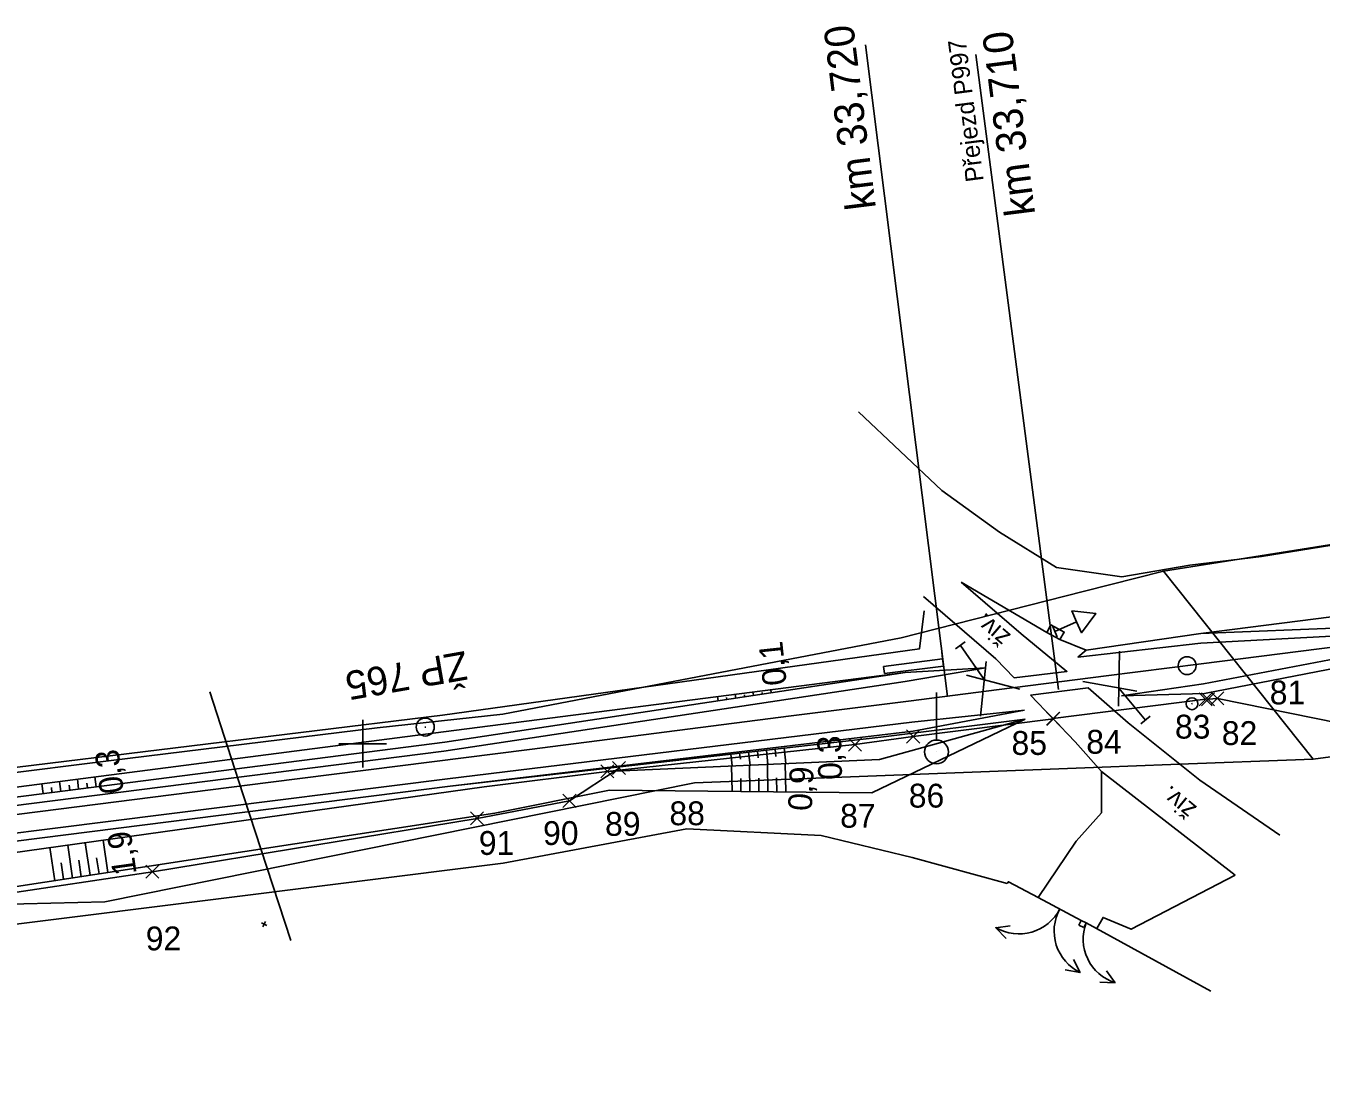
# Model space of a CAD drawing. Extents: x -805011 to -803920, y -1150790 to -1150234.
# Drawn here: x -804628.3 to -804519.6, y -1150528 to -1150439.8 of the extents above; entities that cross this region are included whole.
import ezdxf

# ---------------------------------------------------------------- set-up
doc = ezdxf.new("R2010")
doc.units = 0
for name, color, linetype in [('0381KM032-037P - Vrstva 1', 7, 'Continuous'), ('0381KM032-037P - Vrstva 12', 7, 'Continuous'), ('0381KM032-037P - Vrstva 17', 7, 'Continuous'), ('0381KM032-037P - Vrstva 25', 7, 'Continuous'), ('0381KM032-037P - Vrstva 36', 7, 'Continuous'), ('0381KM032-037P - Vrstva 4', 7, 'Continuous'), ('0381KM032-037P - Vrstva 48', 7, 'Continuous'), ('0381KM032-037P - Vrstva 49', 7, 'Continuous'), ('0381KM032-037P - Vrstva 51', 7, 'Continuous'), ('0381KM032-037P - Vrstva 55', 7, 'Continuous'), ('0381KM032-037P - Vrstva 7', 7, 'Continuous'), ('0381KM032-037P - Vrstva 9', 7, 'Continuous'), ('Default', 7, 'Continuous'), ('hran DP - hran DP', 7, 'Continuous'), ('krizky_1000 - Vrstva 1', 7, 'Continuous'), ('PSR_C2_2_Lomove_body_Vimperk - Vrstva 60', 7, 'Continuous'), ('PSR_C2_2_trasa_Vimperk - Kabelová trasa', 7, 'Continuous'), ('vyt_sit - stávající', 7, 'Continuous')]:
    doc.layers.add(name, color=color, linetype=linetype)

msp = doc.modelspace()

# ---------------------------------------------------------------- linework, layer by layer
at = {"layer": '0381KM032-037P - Vrstva 1'}
msp.add_lwpolyline([(-804485.9, -1150487.74), (-804508.11, -1150490.55), (-804529.67, -1150493.3), (-804537.63, -1150494.31), (-804546.61, -1150495.46), (-804554.2, -1150496.42), (-804564.05, -1150497.67), (-804586.01, -1150500.48), (-804607.92, -1150503.26), (-804630.35, -1150506.11), (-804652.65, -1150508.9), (-804675.7, -1150511.78), (-804698.85, -1150514.71), (-804701.61, -1150515.06), (-804722.18, -1150517.67), (-804729.05, -1150518.54), (-804735.1, -1150519.31), (-804744.56, -1150520.5), (-804767.65, -1150523.46), (-804791, -1150526.42)], dxfattribs=at)
at = {"layer": '0381KM032-037P - Vrstva 12'}
for p, q in [((-804542.27, -1150490.03), (-804542.27, -1150490.03)), ((-804541.15, -1150490.64), (-804541.15, -1150490.64))]:
    msp.add_line(p, q, dxfattribs=at)
msp.add_lwpolyline([(-804542.6, -1150490.68), (-804542.27, -1150490.03), (-804541.15, -1150490.64), (-804541.52, -1150491.26), (-804542.6, -1150490.68), (-804542.27, -1150490.03), (-804541.15, -1150490.64), (-804541.52, -1150491.26)], dxfattribs=at)
at = {"layer": '0381KM032-037P - Vrstva 17'}
for p, q in [((-804553.92, -1150509.55), (-804545.93, -1150511.73)), ((-804546.89, -1150515.44), (-804546.02, -1150516.35)), ((-804539.31, -1150515.02), (-804528.85, -1150520.76)), ((-804539.82, -1150519.19), (-804541.07, -1150518.98)), ((-804536.89, -1150520.06), (-804537.59, -1150519.06)), ((-804538.15, -1150520.02), (-804536.89, -1150520.06)), ((-804536.89, -1150520.06), (-804538.15, -1150520.02))]:
    msp.add_line(p, q, dxfattribs=at)
for points in [[(-804368.54, -1150462.33), (-804374.42, -1150462.03), (-804388.45, -1150464.13), (-804427.08, -1150469.25), (-804429.72, -1150469.73), (-804431.75, -1150470.1), (-804437.24, -1150471.08), (-804446.96, -1150472.02), (-804473.97, -1150476), (-804503.76, -1150480.94), (-804524.61, -1150484.28), (-804530.6, -1150485.02), (-804536.33, -1150485.99), (-804541.81, -1150485.21), (-804546.58, -1150482.25), (-804551.41, -1150478.74), (-804558.4, -1150472.14)], [(-804552.89, -1150488.84), (-804553.29, -1150492.03), (-804593.3, -1150497.6), (-804640.86, -1150503.43), (-804657.42, -1150505.51), (-804657.62, -1150505.23), (-804688.14, -1150507.97), (-804701.71, -1150508.32), (-804722.68, -1150510.59), (-804720.85, -1150507.4)], [(-804731.29, -1150527.98), (-804729.95, -1150523.81), (-804721.9, -1150522.89), (-804700.75, -1150520.73), (-804652.77, -1150518.11), (-804588.21, -1150510.02), (-804572.8, -1150507.15), (-804561.55, -1150507.7), (-804553.92, -1150509.55)], [(-804545.93, -1150511.73), (-804545.83, -1150511.58), (-804543.33, -1150512.91)], [(-804546.02, -1150516.35), (-804546.89, -1150515.44), (-804545.68, -1150515.29)], [(-804539.92, -1150515.23), (-804539.73, -1150514.83), (-804539.31, -1150515.02)], [(-804539.92, -1150515.23), (-804539.5, -1150515.43), (-804539.31, -1150515.02)], [(-804541.07, -1150518.98), (-804539.82, -1150519.19), (-804540.38, -1150518.1)]]:
    msp.add_lwpolyline(points, dxfattribs=at)
for centre, start, end in [((-804544.94, -1150512.13), 239.5292, 333.049), ((-804538.17, -1150515.73), 150.9796, 244.4995), ((-804535.73, -1150516.4), 158.9316, 252.4515)]:
    msp.add_arc(centre, 3.83, start, end, dxfattribs=at)
at = {"layer": '0381KM032-037P - Vrstva 25'}
msp.add_lwpolyline([(-804612.83, -1150495.66), (-804610.41, -1150503.1), (-804608.55, -1150508.81), (-804606.04, -1150516.52)], dxfattribs=at)
at = {"layer": '0381KM032-037P - Vrstva 36'}
for p, q in [((-804551.87, -1150499.69), (-804551.87, -1150495.69)), ((-804551.87, -1150500.69), (-804551.87, -1150500.69))]:
    msp.add_line(p, q, dxfattribs=at)
msp.add_circle((-804551.87, -1150500.69), 1, dxfattribs=at)
at = {"layer": '0381KM032-037P - Vrstva 4'}
for p, q in [((-804541.64, -1150495.45), (-804548.57, -1150442.16)), ((-804515.79, -1150490.21), (-804529.7, -1150490.74)), ((-804549.45, -1150491.46), (-804550.27, -1150492.03)), ((-804515.61, -1150490.8), (-804529.7, -1150491.57)), ((-804549.86, -1150491.75), (-804547.86, -1150494.62)), ((-804529.7, -1150491.57), (-804540.01, -1150492.74)), ((-804536.6, -1150496.85), (-804536.52, -1150492.24)), ((-804515.43, -1150492.3), (-804529.48, -1150494.97)), ((-804547.76, -1150493.63), (-804554.49, -1150494.02)), ((-804547.76, -1150493.63), (-804554.48, -1150494.77)), ((-804547.69, -1150493.1), (-804548.16, -1150497.69)), ((-804515.37, -1150493.06), (-804529.38, -1150495.79)), ((-804593.19, -1150500.62), (-804554.48, -1150494.77)), ((-804593.11, -1150499.86), (-804554.49, -1150494.02)), ((-804544.88, -1150495.41), (-804549.34, -1150494.25)), ((-804537.63, -1150494.31), (-804546.61, -1150495.46)), ((-804539.6, -1150494.79), (-804535.05, -1150495.58)), ((-804534.33, -1150498.02), (-804536.56, -1150495.33)), ((-804536.34, -1150495.99), (-804529.48, -1150494.97)), ((-804529.38, -1150495.79), (-804536.34, -1150495.99)), ((-804544.49, -1150497.19), (-804553.94, -1150498.18)), ((-804553.83, -1150498.96), (-804544.49, -1150497.19)), ((-804534.71, -1150498.34), (-804533.94, -1150497.7)), ((-804553.94, -1150498.18), (-804592.89, -1150502.96)), ((-804592.67, -1150503.55), (-804553.83, -1150498.96))]:
    msp.add_line(p, q, dxfattribs=at)
for points in [[(-804540.01, -1150492.74), (-804539.3, -1150492.14), (-804529.7, -1150490.74)], [(-804593.11, -1150499.86), (-804640.49, -1150505.94), (-804687.8, -1150511.91), (-804699.22, -1150512.12)], [(-804593.19, -1150500.62), (-804640.38, -1150506.6), (-804687.82, -1150512.54), (-804699.1, -1150513.12)], [(-804592.89, -1150502.96), (-804640.05, -1150508.88), (-804687.61, -1150514.59), (-804699.07, -1150516.32)], [(-804592.67, -1150503.55), (-804639.94, -1150509.55), (-804687.3, -1150515.71), (-804688.22, -1150515.92)]]:
    msp.add_lwpolyline(points, dxfattribs=at)
at = {"layer": '0381KM032-037P - Vrstva 48'}
for p, q in [((-804568.7, -1150496.17), (-804568.75, -1150495.86)), ((-804567.96, -1150496.06), (-804567.98, -1150495.91)), ((-804567.22, -1150495.94), (-804567.26, -1150495.67)), ((-804566.48, -1150495.83), (-804566.5, -1150495.7)), ((-804565.74, -1150495.72), (-804565.77, -1150495.47)), ((-804570.19, -1150496.39), (-804570.24, -1150496.05)), ((-804569.44, -1150496.28), (-804569.47, -1150496.12)), ((-804569.12, -1150500.87), (-804569.01, -1150501.87)), ((-804568.38, -1150500.79), (-804568.32, -1150501.31)), ((-804567.63, -1150500.7), (-804567.51, -1150501.8)), ((-804566.89, -1150500.62), (-804566.82, -1150501.19)), ((-804566.14, -1150500.53), (-804566.01, -1150501.74)), ((-804565.4, -1150500.45), (-804565.33, -1150501.07)), ((-804564.65, -1150500.36), (-804564.5, -1150501.67)), ((-804569.02, -1150504), (-804569.05, -1150501.87)), ((-804567.52, -1150504.01), (-804567.55, -1150501.8)), ((-804566.02, -1150504.03), (-804566.05, -1150501.74)), ((-804564.51, -1150504.04), (-804564.55, -1150501.67)), ((-804626.81, -1150504.19), (-804626.92, -1150503.36)), ((-804625.33, -1150504), (-804625.43, -1150503.17)), ((-804624.58, -1150503.9), (-804624.63, -1150503.49)), ((-804623.84, -1150503.8), (-804623.94, -1150502.98)), ((-804623.09, -1150503.71), (-804623.15, -1150503.3)), ((-804622.35, -1150503.61), (-804622.46, -1150502.79)), ((-804568.27, -1150504.01), (-804568.28, -1150502.92)), ((-804566.77, -1150504.02), (-804566.78, -1150502.9)), ((-804565.26, -1150504.03), (-804565.28, -1150502.87)), ((-804626.07, -1150504.09), (-804626.12, -1150503.68)), ((-804625.83, -1150511.5), (-804626.24, -1150508.72)), ((-804624.35, -1150511.27), (-804624.75, -1150508.52)), ((-804622.87, -1150511.04), (-804623.27, -1150508.31)), ((-804621.38, -1150510.81), (-804621.78, -1150508.1)), ((-804625.09, -1150511.38), (-804625.29, -1150510)), ((-804623.61, -1150511.16), (-804623.81, -1150509.78)), ((-804622.12, -1150510.93), (-804622.33, -1150509.57))]:
    msp.add_line(p, q, dxfattribs=at)
at = {"layer": '0381KM032-037P - Vrstva 49'}
for p, q in [((-804554.49, -1150494.02), (-804593.11, -1150499.86)), ((-804544.42, -1150497.94), (-804556.53, -1150499.44)), ((-804608.49, -1150515.04), (-804608.04, -1150515.25)), ((-804608.15, -1150514.92), (-804608.37, -1150515.37))]:
    msp.add_line(p, q, dxfattribs=at)
for points in [[(-804541.81, -1150485.21), (-804536.33, -1150485.99), (-804530.6, -1150485.02), (-804524.61, -1150484.28), (-804503.76, -1150480.94), (-804473.97, -1150476), (-804446.96, -1150472.02), (-804437.24, -1150471.08), (-804431.75, -1150470.1), (-804429.72, -1150469.73), (-804427.08, -1150469.25), (-804388.45, -1150464.13), (-804374.42, -1150462.03), (-804368.54, -1150462.33), (-804346.87, -1150460.56), (-804338.71, -1150460.38), (-804328.85, -1150461.67), (-804323.06, -1150462.29), (-804320.34, -1150463.27)], [(-804529.7, -1150490.74), (-804539.3, -1150492.14), (-804541.52, -1150491.26), (-804542.6, -1150490.68), (-804549.8, -1150486.44)], [(-804516.1, -1150489.01), (-804529.7, -1150490.74)], [(-804554.49, -1150494.02), (-804593.21, -1150499.01), (-804640.53, -1150505.12), (-804688.31, -1150508.22), (-804703.24, -1150508.74), (-804722.68, -1150510.59)], [(-804544.42, -1150497.94), (-804556.65, -1150501.33), (-804579.48, -1150502.32), (-804589.81, -1150503.62), (-804675.11, -1150515.57), (-804678.92, -1150516.15)], [(-804544.42, -1150497.94), (-804557.28, -1150504.11), (-804579.29, -1150503.91), (-804588.92, -1150505.83), (-804639.29, -1150513.56), (-804678.92, -1150516.15)], [(-804593.11, -1150499.86), (-804640.49, -1150505.94), (-804687.8, -1150511.91), (-804699.22, -1150512.12)], [(-804556.53, -1150499.44), (-804592.67, -1150503.55), (-804639.94, -1150509.55), (-804678.92, -1150516.15)]]:
    msp.add_lwpolyline(points, dxfattribs=at)
at = {"layer": '0381KM032-037P - Vrstva 51'}
for p, q in [((-804544.77, -1150490.77), (-804549.8, -1150486.44)), ((-804546.9, -1150492.89), (-804552.96, -1150487.64)), ((-804542.14, -1150490.12), (-804541.74, -1150491.03)), ((-804545.36, -1150494.48), (-804546.9, -1150492.89)), ((-804540.22, -1150499.84), (-804543.98, -1150495.94))]:
    msp.add_line(p, q, dxfattribs=at)
for points in [[(-804541.94, -1150490.58), (-804540.11, -1150489.77), (-804539.71, -1150490.69), (-804538.51, -1150489.07), (-804540.51, -1150488.86), (-804540.11, -1150489.77)], [(-804545.36, -1150494.48), (-804540.93, -1150493.94), (-804544.77, -1150490.77)], [(-804543.98, -1150495.94), (-804539.14, -1150495.31), (-804535.78, -1150498.25)], [(-804535.78, -1150498.25), (-804529.76, -1150503.07), (-804523.07, -1150507.67)], [(-804540.22, -1150499.84), (-804538.01, -1150502.34), (-804526.8, -1150511.03)], [(-804538.01, -1150502.34), (-804538.01, -1150505.79), (-804540.15, -1150508.19), (-804543.33, -1150512.91), (-804539.73, -1150514.83)], [(-804538.41, -1150515.52), (-804537.89, -1150514.57), (-804535.54, -1150515.57), (-804526.8, -1150511.03)]]:
    msp.add_lwpolyline(points, dxfattribs=at)
at = {"layer": '0381KM032-037P - Vrstva 55'}
msp.add_line((-804532.83, -1150485.53), (-804520.26, -1150501.29), dxfattribs=at)
at = {"layer": '0381KM032-037P - Vrstva 7'}
msp.add_line((-804530.38, -1150496.64), (-804530.48, -1150496.66), dxfattribs=at)
for centre, radius in [((-804530.84, -1150493.45), 0.75), ((-804530.43, -1150496.65), 0.5)]:
    msp.add_circle(centre, radius, dxfattribs=at)
at = {"layer": '0381KM032-037P - Vrstva 9'}
for p, q in [((-804550.95, -1150496.05), (-804557.83, -1150441.36)), ((-804551.35, -1150492.89), (-804551.42, -1150492.3)), ((-804551.35, -1150492.89), (-804556.31, -1150493.51)), ((-804556.31, -1150493.51), (-804556.24, -1150494.1)), ((-804556.24, -1150494.1), (-804551.28, -1150493.49)), ((-804551.28, -1150493.49), (-804551.35, -1150492.89))]:
    msp.add_line(p, q, dxfattribs=at)
at = {"layer": 'hran DP - hran DP'}
for p, q in [((-804532.83, -1150485.53), (-804473.24, -1150476.04)), ((-804539.55, -1150487.24), (-804532.83, -1150485.53)), ((-804554.84, -1150491.12), (-804539.55, -1150487.24)), ((-804574.54, -1150494.89), (-804554.84, -1150491.12)), ((-804588.25, -1150497.51), (-804574.54, -1150494.89)), ((-804477.16, -1150495.64), (-804520.26, -1150501.29)), ((-804598.8, -1150498.68), (-804588.25, -1150497.51)), ((-804621.33, -1150501.45), (-804598.8, -1150498.68)), ((-804520.26, -1150501.29), (-804532.2, -1150501.75)), ((-804634.52, -1150503.07), (-804621.33, -1150501.45)), ((-804537.98, -1150501.97), (-804572.18, -1150503.29)), ((-804532.2, -1150501.75), (-804537.98, -1150501.97)), ((-804572.18, -1150503.29), (-804621.63, -1150513.27)), ((-804621.63, -1150513.27), (-804664.68, -1150514.39))]:
    msp.add_line(p, q, dxfattribs=at)
at = {"layer": 'krizky_1000 - Vrstva 1'}
for points in [[(-804600, -1150498), (-804600, -1150502)], [(-804602, -1150500), (-804598, -1150500)]]:
    msp.add_lwpolyline(points, dxfattribs=at)
at = {"layer": 'PSR_C2_2_Lomove_body_Vimperk - Vrstva 60'}
for p, q in [((-804529.84, -1150496.82), (-804528.74, -1150495.72)), ((-804528.74, -1150496.82), (-804529.84, -1150495.72)), ((-804529.63, -1150496.82), (-804528.53, -1150495.72)), ((-804528.53, -1150496.82), (-804529.63, -1150495.72)), ((-804528.85, -1150496.75), (-804527.75, -1150495.65)), ((-804527.75, -1150496.75), (-804528.85, -1150495.65)), ((-804542.65, -1150498.44), (-804541.55, -1150497.34)), ((-804541.55, -1150498.44), (-804542.65, -1150497.34)), ((-804542.61, -1150498.46), (-804541.51, -1150497.36)), ((-804541.51, -1150498.46), (-804542.61, -1150497.36)), ((-804554.37, -1150499.95), (-804553.27, -1150498.85)), ((-804553.27, -1150499.95), (-804554.37, -1150498.85)), ((-804559.26, -1150500.63), (-804558.16, -1150499.53)), ((-804558.16, -1150500.63), (-804559.26, -1150499.53)), ((-804580.03, -1150502.87), (-804578.93, -1150501.77)), ((-804578.93, -1150502.87), (-804580.03, -1150501.77)), ((-804579.05, -1150502.59), (-804577.95, -1150501.49)), ((-804577.95, -1150502.59), (-804579.05, -1150501.49)), ((-804583.2, -1150505.34), (-804582.1, -1150504.24)), ((-804582.1, -1150505.34), (-804583.2, -1150504.24)), ((-804590.96, -1150506.82), (-804589.86, -1150505.72)), ((-804589.86, -1150506.82), (-804590.96, -1150505.72)), ((-804618.19, -1150511.29), (-804617.09, -1150510.19)), ((-804617.09, -1150511.29), (-804618.19, -1150510.19))]:
    msp.add_line(p, q, dxfattribs=at)
at = {"layer": 'PSR_C2_2_trasa_Vimperk - Kabelová trasa'}
for p, q in [((-804529.29, -1150496.27), (-804542.1, -1150497.89)), ((-804542.06, -1150497.91), (-804553.82, -1150499.4)), ((-804558.71, -1150500.08), (-804579.48, -1150502.32)), ((-804558.71, -1150500.08), (-804553.82, -1150499.4)), ((-804582.65, -1150504.79), (-804578.5, -1150502.04)), ((-804582.65, -1150504.79), (-804590.41, -1150506.27)), ((-804617.64, -1150510.74), (-804590.41, -1150506.27)), ((-804634.35, -1150513.26), (-804617.64, -1150510.74))]:
    msp.add_line(p, q, dxfattribs=at)
msp.add_lwpolyline([(-804529.08, -1150496.27), (-804528.3, -1150496.2), (-804516.01, -1150498.69), (-804469.46, -1150493.33), (-804431.1, -1150489.42), (-804404.84, -1150486.85), (-804374.84, -1150483.32), (-804363.68, -1150482.47), (-804347.01, -1150481.54), (-804340.82, -1150481.2), (-804326.33, -1150481.6), (-804317.79, -1150482), (-804308.33, -1150484.14), (-804289, -1150488.51)], dxfattribs=at)
at = {"layer": 'vyt_sit - stávající'}
msp.add_line((-804594.8, -1150498.6), (-804594.7, -1150498.6), dxfattribs=at)
msp.add_circle((-804594.75, -1150498.6), 0.756, dxfattribs=at)

# ---------------------------------------------------------------- texts
at = {"layer": '0381KM032-037P - Vrstva 4'}
for s, height, p in [('km 33,710', 2.5, (-804543.58, -1150455.56)), ('Přejezd P997', 1.5, (-804547.9, -1150452.76))]:
    msp.add_text(s, height=height, rotation=97.2836, dxfattribs=at).set_placement(p)
at = {"layer": '0381KM032-037P - Vrstva 48'}
for s, rotation, p in [('0,1', 96.0264, (-804564.42, -1150495.02)), ('0,3', 91.5025, (-804559.78, -1150503.01)), ('0,3', 97.3526, (-804620.03, -1150504.07)), ('0,9', 87.4636, (-804562.33, -1150505.67)), ('1,9', 97.9771, (-804618.96, -1150510.9))]:
    msp.add_text(s, height=2, rotation=rotation, dxfattribs=at).set_placement(p)
at = {"layer": '0381KM032-037P - Vrstva 51'}
for rotation, p in [(139.2713, (-804545.56, -1150490.88)), (140.5584, (-804529.95, -1150505.32))]:
    msp.add_text('živ.', height=1.5, rotation=rotation, dxfattribs=at).set_placement(p)
at = {"layer": '0381KM032-037P - Vrstva 9'}
msp.add_text('km 33,720', height=2.5, rotation=97.0859, dxfattribs=at).set_placement((-804556.94, -1150455.05))
at = {"layer": 'Default'}
for s, p in [('81', (-804523.91, -1150496.7)), ('83', (-804531.86, -1150499.57)), ('82', (-804527.93, -1150500.11)), ('85', (-804545.57, -1150500.94)), ('84', (-804539.3, -1150500.84)), ('86', (-804554.19, -1150505.36)), ('88', (-804574.27, -1150506.84)), ('87', (-804559.95, -1150507.05)), ('90', (-804584.87, -1150508.5)), ('89', (-804579.67, -1150507.73)), ('91', (-804590.26, -1150509.33)), ('92', (-804618.2, -1150517.34))]:
    msp.add_text(s, height=2, dxfattribs=at).set_placement(p)
at = {"layer": 'vyt_sit - stávající'}
msp.add_text('ŽP 765', height=2.4, rotation=190, dxfattribs=at).set_placement((-804591.41, -1150492.21))

doc.saveas('drawing.dxf')
